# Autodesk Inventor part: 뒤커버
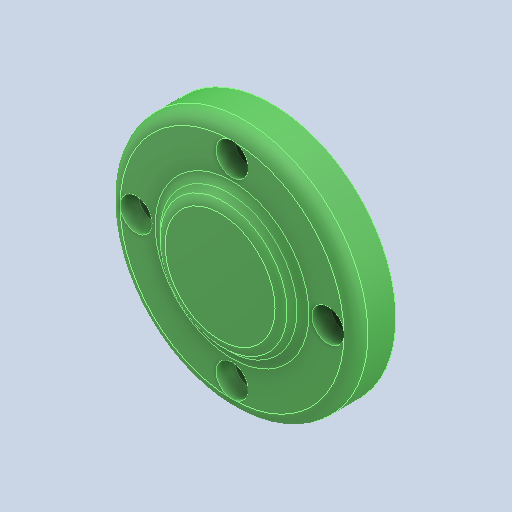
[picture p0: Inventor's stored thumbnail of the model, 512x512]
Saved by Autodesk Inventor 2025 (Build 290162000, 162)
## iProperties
Created: 2024-07
Part Number: 뒤커버
Material: 알루미늄 6061
Document SubType Name: Modeling
Designer: anfro
Density: 2.71 g/cm^3
Appearance: 기본값
Author: jhkim
Sending System: Autodesk Inventor 2025
Preprocessor: ST-DEVELOPER v20
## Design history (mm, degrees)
feature "솔리드1"
node "솔리드2"
